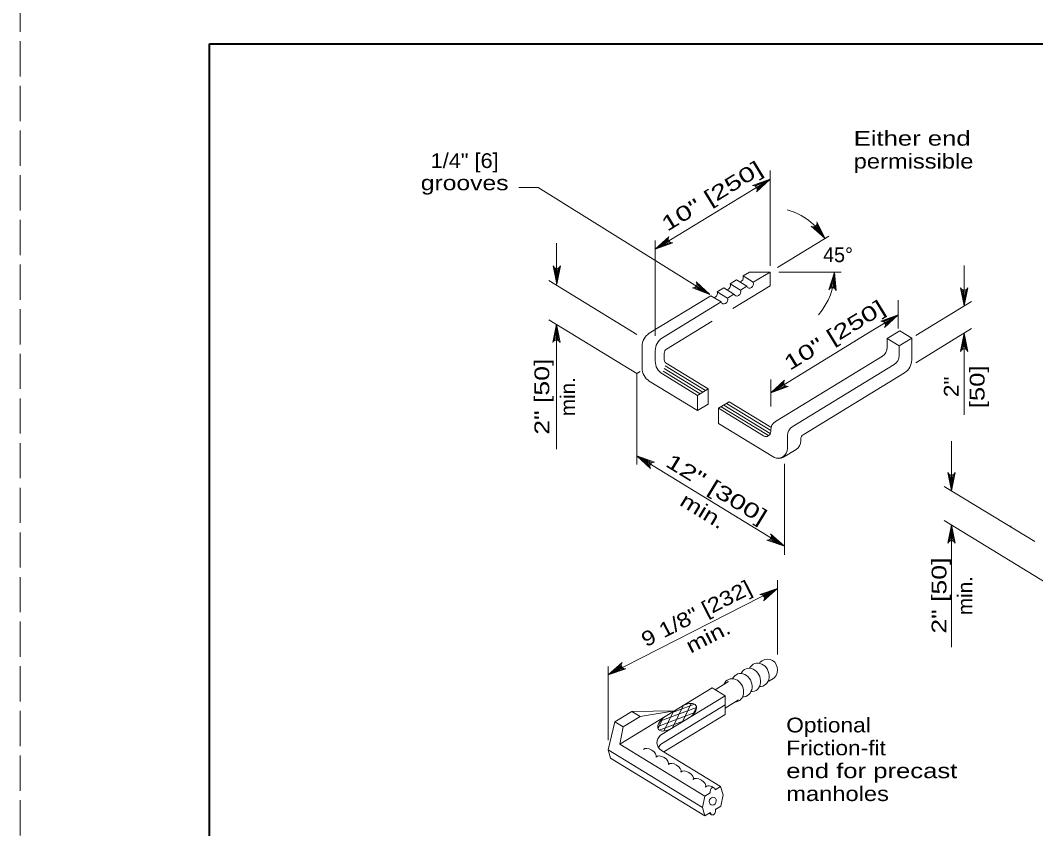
# Model space of a CAD drawing. Extents: x 1083.1 to 1117.1, y 697.4 to 741.4.
# Drawn here: x 1083.13 to 1093.86, y 710.56 to 719.1 of the extents above; entities that cross this region are included whole.
import ezdxf
from ezdxf.enums import TextEntityAlignment as Align

# ---------------------------------------------------------------- set-up
doc = ezdxf.new("R2010")
doc.units = 0
doc.header["$LTSCALE"] = 0.062
doc.linetypes.add('LONG_DASHED', pattern=[7.5, 6, -1.5])
doc.layers.add('1', color=7, linetype='Continuous', lineweight=13)

msp = doc.modelspace()

# ---------------------------------------------------------------- linework, layer by layer
at = {"layer": '1', "lineweight": 25}
msp.add_line((1085.12642, 718.85408), (1116.62642, 718.85408), dxfattribs=at)
at = {"layer": '1'}
for p, q in [((1091.05508, 716.509), (1091.05508, 717.51783)), ((1089.8405, 716.68325), (1091.05508, 717.42558)), ((1090.89017, 717.35567), (1091.05508, 717.42558)), ((1090.90183, 717.3495), (1091.05508, 717.42558)), ((1090.91275, 717.33775), (1091.05508, 717.42558)), ((1090.91767, 717.32633), (1091.05508, 717.42558)), ((1090.919, 717.31292), (1091.05508, 717.42558)), ((1091.53583, 716.92942), (1091.63758, 716.79667)), ((1091.54642, 716.94142), (1091.63758, 716.79667)), ((1091.55133, 716.95367), (1091.63758, 716.79667)), ((1091.13442, 716.49142), (1091.67692, 716.82292)), ((1091.51167, 716.92067), (1091.63758, 716.79667)), ((1091.52492, 716.92333), (1091.63758, 716.79667)), ((1088.79483, 716.3145), (1088.79483, 716.74958)), ((1089.9775, 716.79483), (1089.8405, 716.68325)), ((1089.97867, 716.78142), (1089.8405, 716.68325)), ((1089.8405, 715.76658), (1089.8405, 716.77542)), ((1089.98358, 716.76992), (1089.8405, 716.68325)), ((1089.99433, 716.75808), (1089.8405, 716.68325)), ((1090.006, 716.75183), (1089.8405, 716.68325)), ((1093.108, 716.51342), (1093.108, 716.084)), ((1088.77458, 716.4895), (1088.79908, 716.3145)), ((1088.78675, 716.48358), (1088.79908, 716.3145)), ((1088.82617, 716.49158), (1088.79908, 716.3145)), ((1088.81483, 716.48483), (1088.79908, 716.3145)), ((1088.79908, 716.48175), (1088.79908, 716.3145)), ((1090.76908, 716.401), (1090.83725, 716.44267)), ((1090.87783, 716.3345), (1090.76908, 716.401)), ((1090.83725, 716.44267), (1091.05508, 716.44267)), ((1090.87783, 716.3345), (1091.05508, 716.44283)), ((1091.05508, 716.29775), (1091.05508, 716.44267)), ((1091.14675, 716.44283), (1091.80542, 716.44283)), ((1091.68933, 716.27008), (1091.73658, 716.44283)), ((1091.70133, 716.2755), (1091.73658, 716.44283)), ((1091.71733, 716.27675), (1091.73658, 716.44283)), ((1091.72942, 716.2735), (1091.73658, 716.44283)), ((1091.74075, 716.26617), (1091.73658, 716.44283)), ((1089.646, 715.78317), (1088.71617, 716.3515)), ((1090.27583, 716.29417), (1090.41817, 716.20633)), ((1090.2815, 716.30917), (1090.41817, 716.20633)), ((1090.28175, 716.32233), (1090.41817, 716.20633)), ((1090.63267, 716.31758), (1090.70083, 716.35933)), ((1090.74142, 716.25117), (1090.63267, 716.31758)), ((1090.66283, 716.058), (1091.05508, 716.29775)), ((1090.80958, 716.29283), (1090.70083, 716.35933)), ((1090.74142, 716.25117), (1090.80958, 716.29283)), ((1089.77725, 715.79475), (1090.428, 716.19258)), ((1090.25642, 716.27742), (1090.41817, 716.20633)), ((1090.26783, 716.28458), (1090.41817, 716.20633)), ((1090.53683, 716.12608), (1090.428, 716.19258)), ((1090.49625, 716.23425), (1090.56442, 716.27592)), ((1090.605, 716.16775), (1090.49625, 716.23425)), ((1090.67325, 716.2095), (1090.56442, 716.27592)), ((1090.605, 716.16775), (1090.67325, 716.2095)), ((1093.0835, 716.259), (1093.108, 716.084)), ((1093.09558, 716.25308), (1093.108, 716.084)), ((1093.135, 716.26108), (1093.108, 716.084)), ((1093.12367, 716.25442), (1093.108, 716.084)), ((1093.108, 716.25133), (1093.108, 716.084)), ((1089.91567, 715.74642), (1090.53683, 716.12608)), ((1092.41025, 715.84475), (1092.41025, 716.1435)), ((1092.5955, 715.77075), (1093.18667, 716.13208)), ((1092.24533, 715.92117), (1092.41025, 715.99092)), ((1092.25692, 715.915), (1092.41025, 715.99092)), ((1092.26783, 715.90325), (1092.41025, 715.99092)), ((1092.27275, 715.89175), (1092.41025, 715.99092)), ((1092.27408, 715.87833), (1092.41025, 715.99092)), ((1089.646, 715.37), (1088.71617, 715.93833)), ((1088.76783, 715.71325), (1088.79483, 715.89025)), ((1088.77917, 715.71992), (1088.79483, 715.89025)), ((1088.79483, 715.723), (1088.79483, 715.89025)), ((1088.80725, 715.72117), (1088.79483, 715.89025)), ((1088.81933, 715.71525), (1088.79483, 715.89025)), ((1088.79483, 714.56808), (1088.79483, 715.89025)), ((1089.96058, 715.62875), (1090.444, 715.92425)), ((1092.29283, 715.73975), (1092.42708, 715.82183)), ((1092.55308, 715.74483), (1092.42708, 715.82183)), ((1092.5955, 715.48325), (1093.18667, 715.84458)), ((1093.08092, 715.61942), (1093.108, 715.7965)), ((1093.09225, 715.62617), (1093.108, 715.7965)), ((1093.108, 715.62925), (1093.108, 715.7965)), ((1093.12033, 715.62742), (1093.108, 715.7965)), ((1093.13242, 715.6215), (1093.108, 715.7965)), ((1093.108, 715.7965), (1093.108, 714.933)), ((1089.70208, 715.42708), (1089.70208, 715.65692)), ((1092.41875, 715.66283), (1092.29283, 715.73975)), ((1092.29283, 715.6465), (1092.29283, 715.73975)), ((1092.41875, 715.66283), (1092.55308, 715.74483)), ((1092.41875, 715.55858), (1092.41875, 715.66283)), ((1092.55308, 715.51542), (1092.55308, 715.74483)), ((1089.8405, 715.50292), (1089.8405, 715.60858)), ((1089.93558, 715.51533), (1089.93558, 715.58317)), ((1091.11158, 714.86325), (1092.24275, 715.55467)), ((1090.37142, 715.19008), (1089.9455, 715.45042)), ((1090.39967, 715.20733), (1089.9555, 715.47883)), ((1091.28925, 714.80692), (1092.36867, 715.46667)), ((1089.646, 715.37), (1089.68242, 715.39225)), ((1089.646, 715.37), (1089.646, 714.40642)), ((1090.28675, 715.13833), (1089.91567, 715.36508)), ((1090.315, 715.15558), (1089.92558, 715.3935)), ((1090.34317, 715.17283), (1089.93558, 715.422)), ((1091.40467, 714.72158), (1092.47792, 715.37758)), ((1090.28675, 714.97833), (1089.77683, 715.29)), ((1091.0615, 715.02033), (1091.0615, 715.30717)), ((1091.19875, 715.27775), (1091.0615, 715.16642)), ((1091.19992, 715.26425), (1091.0615, 715.16642)), ((1091.20475, 715.25275), (1091.0615, 715.16642)), ((1091.2155, 715.24092), (1091.0615, 715.16642)), ((1091.22708, 715.23467), (1091.0615, 715.16642)), ((1090.28675, 715.13833), (1090.39967, 715.20733)), ((1090.28675, 714.97833), (1090.28675, 715.13833)), ((1090.39967, 715.04733), (1090.39967, 715.20733)), ((1090.28675, 714.97833), (1090.39967, 715.04733)), ((1090.50992, 715.00192), (1090.62275, 715.07092)), ((1090.98633, 714.71067), (1090.50992, 715.00192)), ((1090.50992, 714.84192), (1090.50992, 715.00192)), ((1091.0395, 714.71267), (1090.53808, 715.01917)), ((1091.05758, 714.73617), (1090.56633, 715.03642)), ((1091.0615, 714.76825), (1090.59458, 715.05367)), ((1091.0615, 714.80275), (1090.62275, 715.07092)), ((1091.09558, 714.48392), (1090.50992, 714.84192)), ((1091.0615, 714.75658), (1091.0615, 714.77133)), ((1091.23917, 714.57992), (1091.23917, 714.715)), ((1091.37958, 714.6575), (1091.37958, 714.67567)), ((1092.97308, 714.1285), (1092.97308, 714.65542)), ((1089.78908, 714.412), (1089.646, 714.49867)), ((1089.78358, 714.397), (1089.646, 714.49867)), ((1089.78342, 714.38383), (1089.646, 714.49867)), ((1089.797, 714.42167), (1089.646, 714.49867)), ((1089.80833, 714.429), (1089.646, 714.49867)), ((1089.646, 714.49867), (1091.20825, 713.54367)), ((1091.19583, 714.48392), (1091.3295, 714.56567)), ((1091.20825, 714.41508), (1091.20825, 713.4515)), ((1092.94867, 714.30342), (1092.97308, 714.1285)), ((1092.96075, 714.2975), (1092.97308, 714.1285)), ((1093.00017, 714.3055), (1092.97308, 714.1285)), ((1092.98883, 714.29883), (1092.97308, 714.1285)), ((1092.97308, 714.29575), (1092.97308, 714.1285)), ((1093.855, 713.59333), (1092.89442, 714.17617)), ((1095.45392, 712.25225), (1092.89442, 713.81675)), ((1092.94867, 713.59367), (1092.97308, 713.76867)), ((1092.96075, 713.59958), (1092.97308, 713.76867)), ((1092.97308, 713.60142), (1092.97308, 713.76867)), ((1092.98883, 713.59825), (1092.97308, 713.76867)), ((1093.00017, 713.59158), (1092.97308, 713.76867)), ((1092.97308, 712.47642), (1092.97308, 713.76867)), ((1093.60242, 713.75908), (1093.60242, 713.74617)), ((1091.04442, 713.61), (1091.20825, 713.54367)), ((1091.05558, 713.6175), (1091.20825, 713.54367)), ((1091.06333, 713.62733), (1091.20825, 713.54367)), ((1091.06842, 713.65567), (1091.20825, 713.54367)), ((1091.06858, 713.6425), (1091.20825, 713.54367)), ((1091.135, 713.18517), (1091.135, 712.4)), ((1089.3425, 712.18342), (1091.135, 713.09683)), ((1090.96817, 713.03175), (1091.135, 713.09683)), ((1090.97958, 713.02533), (1091.135, 713.09683)), ((1090.99017, 713.01325), (1091.135, 713.09683)), ((1090.99475, 713.00167), (1091.135, 713.09683)), ((1090.99567, 712.98817), (1091.135, 713.09683)), ((1090.94192, 712.313), (1090.973, 712.332)), ((1089.48183, 712.29208), (1089.3425, 712.18342)), ((1089.48275, 712.27867), (1089.3425, 712.18342)), ((1089.3425, 711.49467), (1089.3425, 712.27167)), ((1089.48742, 712.267), (1089.3425, 712.18342)), ((1089.49792, 712.255), (1089.3425, 712.18342)), ((1089.50942, 712.2485), (1089.3425, 712.18342)), ((1090.473, 712.02642), (1090.614, 712.11258)), ((1091.04342, 712.11567), (1091.08475, 712.141)), ((1089.46767, 711.44975), (1090.442, 712.04533)), ((1090.579, 711.96158), (1090.442, 712.04533)), ((1089.89792, 711.54525), (1090.579, 711.96158)), ((1090.579, 711.76525), (1090.579, 711.96158)), ((1090.579, 711.83183), (1090.72008, 711.91808)), ((1089.41383, 711.68617), (1089.59375, 711.79608)), ((1089.59375, 711.79608), (1090.0435, 711.8025)), ((1090.0435, 711.8025), (1089.67975, 711.74358)), ((1089.86675, 711.63883), (1090.25883, 711.78583)), ((1089.89075, 711.69242), (1090.27792, 711.8375)), ((1089.90667, 711.45475), (1090.579, 711.86575)), ((1089.93292, 711.58975), (1090.02917, 711.793)), ((1090.01158, 711.78225), (1090.2565, 711.87408)), ((1090.02317, 711.62192), (1090.13425, 711.85658)), ((1090.1285, 711.68617), (1090.22108, 711.88175)), ((1090.23942, 711.762), (1090.27767, 711.84283)), ((1089.41383, 711.68617), (1089.3425, 711.39033)), ((1089.49983, 711.63358), (1089.41383, 711.68617)), ((1089.87017, 711.61558), (1089.92208, 711.72517)), ((1089.88275, 711.60033), (1090.15492, 711.70233)), ((1089.93008, 711.36858), (1090.579, 711.76525)), ((1089.46767, 711.44975), (1089.49983, 711.63358)), ((1090.33992, 710.78075), (1089.3425, 711.39033)), ((1089.3425, 711.39033), (1089.369, 711.30217)), ((1090.36542, 710.901), (1089.46767, 711.44975)), ((1090.53058, 711.00158), (1089.906, 711.38333)), ((1090.36642, 710.69258), (1089.369, 711.30217)), ((1090.36567, 710.90083), (1090.42142, 710.93483)), ((1090.47483, 710.9675), (1090.53058, 711.00158)), ((1090.36542, 710.901), (1090.33992, 710.78075)), ((1090.33992, 710.78075), (1090.36642, 710.69258)), ((1090.36642, 710.69258), (1090.42325, 710.72733)), ((1090.437, 710.70433), (1090.41133, 710.72008)), ((1090.47667, 710.76), (1090.53358, 710.79475))]:
    msp.add_line(p, q, dxfattribs=at)
at = {"layer": '1', "linetype": 'LONG_DASHED'}
msp.add_lwpolyline([(1083.12642, 697.35408), (1117.12642, 697.35408), (1117.12642, 719.35408), (1083.12642, 719.35408)], close=True, dxfattribs=at)
at = {"layer": '1', "lineweight": 25}
msp.add_lwpolyline([(1116.62642, 697.85408), (1085.12642, 697.85408), (1085.12642, 718.85408)], dxfattribs=at)
at = {"layer": '1', "lineweight": 40}
msp.add_lwpolyline([(1085.12642, 718.85408), (1116.62642, 718.85408), (1116.62642, 697.85408), (1085.12642, 697.85408)], close=True, dxfattribs=at)
at = {"layer": '1'}
for points in [[(1090.87025, 717.357), (1091.05508, 717.42558), (1090.91092, 717.29117)], [(1090.41817, 716.20633), (1088.60167, 717.33642), (1088.39783, 717.33642)], [(1091.55067, 716.97358), (1091.63758, 716.79667), (1091.48933, 716.92658)], [(1090.02583, 716.75033), (1089.8405, 716.68325), (1089.98575, 716.8165)], [(1088.83775, 716.50783), (1088.79908, 716.3145), (1088.76042, 716.50783)], [(1091.67592, 716.25533), (1091.73658, 716.44283), (1091.75267, 716.24642)], [(1090.274, 716.34075), (1090.41817, 716.20633), (1090.23342, 716.275)], [(1093.14667, 716.27733), (1093.108, 716.084), (1093.06933, 716.27733)], [(1091.0615, 715.16642), (1092.07833, 715.788), (1092.41025, 715.99092)], [(1092.22542, 715.92258), (1092.41025, 715.99092), (1092.26592, 715.85667)], [(1088.75617, 715.697), (1088.79483, 715.89025), (1088.8335, 715.697)], [(1093.06933, 715.60325), (1093.108, 715.7965), (1093.14667, 715.60325)], [(1091.247, 715.23308), (1091.0615, 715.16642), (1091.20708, 715.29933)], [(1089.79133, 714.3655), (1089.646, 714.49867), (1089.83133, 714.43167)], [(1093.01175, 714.32175), (1092.97308, 714.1285), (1092.9345, 714.32175)], [(1093.01175, 713.57533), (1092.97308, 713.76867), (1092.9345, 713.57533)], [(1091.06017, 713.67383), (1091.20825, 713.54367), (1091.0215, 713.60683)], [(1090.94825, 713.03367), (1091.135, 713.09683), (1090.98692, 712.96675)], [(1089.52925, 712.24658), (1089.3425, 712.18342), (1089.49058, 712.3135)], [(1089.49983, 711.63358), (1089.67975, 711.74358), (1089.59375, 711.79608)], [(1090.53058, 711.00158), (1090.55817, 710.91417), (1090.53358, 710.79475)]]:
    msp.add_lwpolyline(points, dxfattribs=at)
for centre, radius, start, end in [((1090.87731, 717.31587), 0.04172, 323.77224, 99.59836), ((1091.05505, 716.44286), 0.68155, 31.27446, 74.61214), ((1091.51044, 716.96244), 0.04172, 239.55992, 15.38605), ((1090.01915, 716.79155), 0.04172, 143.31059, 279.13672), ((1088.79905, 716.52342), 0.04172, 202.08782, 337.91395), ((1091.05505, 716.44286), 0.68155, 318.5438, 0), ((1090.24041, 716.31604), 0.04172, 260.393, 36.21913), ((1091.71254, 716.23535), 0.04172, 15.45965, 151.28578), ((1093.10793, 716.29294), 0.04172, 202.08782, 337.91395), ((1092.23237, 715.88141), 0.04172, 323.68447, 99.5106), ((1088.79491, 715.68136), 0.04172, 22.08782, 157.91395), ((1093.10801, 715.58761), 0.04172, 22.08782, 157.91395), ((1091.24039, 715.27428), 0.04172, 143.15536, 278.98149), ((1089.82472, 714.39051), 0.04172, 80.90657, 216.7327), ((1092.97308, 714.33736), 0.04172, 202.08782, 337.91395), ((1091.02729, 713.64812), 0.04172, 262.08782, 37.91395), ((1092.97308, 713.55974), 0.04172, 22.08605, 157.91218), ((1090.95412, 712.99239), 0.04172, 322.08782, 97.91395), ((1089.52343, 712.2879), 0.04172, 142.08782, 277.91395)]:
    msp.add_arc(centre, radius, start, end, dxfattribs=at)
for centre, major_axis, ratio, start_param, end_param in [((1090.7349, 716.38035), (-0.01622, -0.0397), 0.836208, 0.44657163, 2.41466889), ((1090.59848, 716.29697), (-0.01622, -0.0397), 0.836208, 0.44657163, 2.41466889), ((1090.84365, 716.31388), (-0.01622, -0.0397), 0.836208, 5.56708016, 8.69785148), ((1090.46207, 716.21359), (-0.01622, -0.0397), 0.836208, 0.44657163, 2.41466889), ((1090.70723, 716.2305), (-0.01622, -0.0397), 0.836208, 5.56708016, 8.69785148), ((1090.57082, 716.14712), (-0.01622, -0.0397), 0.836208, 5.56708016, 8.69785148), ((1089.85241, 715.65695), (0, 0.15913), 0.944544, 0.52359902, 1.57078915), ((1089.99083, 715.60861), (0, 0.15913), 0.944544, 0.52359916, 1.5707956), ((1092.19263, 715.6465), (0, -0.10608), 0.944544, 0.52359882, 1.57078455), ((1089.98566, 715.5828), (0, 0.05304), 0.944544, 0.51976807, 1.57561111), ((1092.31857, 715.55856), (0, -0.10608), 0.944544, 0.52359892, 1.57079865), ((1089.85241, 715.42757), (0, 0.15913), 0.944544, 1.56615671, 2.62169853), ((1089.99083, 715.50292), (0, -0.15913), 0.944544, 4.71239368, 5.75959201), ((1089.97535, 715.51531), (0, 0.04213), 0.944544, 1.5707669, 2.61799669), ((1092.40275, 715.51543), (0, -0.15913), 0.944544, 0.52359848, 1.57078968), ((1091.16167, 714.77134), (0, 0.10608), 0.944544, 0.52359853, 1.57080088), ((1091.33934, 714.71502), (0, -0.10608), 0.944544, 3.66519157, 4.71239102), ((1091.01137, 714.75662), (0, -0.05304), 0.944544, 5.7595893, 7.85398202), ((1091.42972, 714.67568), (0, 0.05304), 0.944544, 0.52359848, 1.57079492), ((1091.13894, 714.57994), (0, 0.10608), 0.944544, 2.61799625, 4.71239111), ((1091.27942, 714.6575), (0, 0.10608), 0.944544, 3.66519376, 4.71241695), ((1091.14573, 714.57578), (0, -0.10608), 0.944544, 5.75958789, 6.80678573), ((1091.14573, 714.57578), (0, -0.10608), 0.944544, 5.75958847, 6.80678646), ((1090.9351, 712.18396), (0.04509, -0.11803), 0.84831, 5.92777232, 10.09288316), ((1091.02889, 712.23652), (0, 0.11235), 0.944544, 3.63436833, 6.8376226), ((1090.75511, 712.07395), (0.04509, -0.11803), 0.84831, 5.92780713, 10.09285582), ((1090.8451, 712.12895), (0.04509, -0.11803), 0.84831, 5.92780713, 10.09285582), ((1090.66512, 712.01894), (0.04509, -0.11803), 0.84831, 6.01711466, 10.14097445), ((1090.15487, 711.78526), (-0.11672, -0.07513), 0.518617, 1.71301598, 4.57774803), ((1089.98958, 711.68584), (-0.11672, -0.07513), 0.518617, 4.8564823, 7.85408437), ((1089.99429, 711.46713), (0.13528, -0.00111), 0.819908, 2.37070385, 4.00778157), ((1090.00122, 711.37516), (0.13528, -0.00111), 0.819908, 2.35146964, 2.78176084), ((1089.78283, 711.35313), (-0.06542, 0.03968), 0.537699, 3.15958152, 6.25223664), ((1089.91371, 711.27401), (-0.06542, 0.03968), 0.537699, 3.15958152, 6.25223664), ((1090.0446, 711.1949), (-0.06542, 0.03968), 0.537699, 3.15958152, 6.25223664), ((1090.17548, 711.11578), (-0.06542, 0.03968), 0.537699, 3.15958152, 6.25223664), ((1090.30637, 711.03667), (-0.06542, 0.03968), 0.537699, 3.15958152, 6.25223664), ((1090.43694, 710.95698), (-0.06542, 0.03968), 0.537699, 4.61023244, 6.25495553), ((1090.44812, 710.9512), (-0.00616, -0.04177), 0.647013, 2.06564711, 5.20714963), ((1090.44999, 710.74366), (-0.00616, -0.04177), 0.647013, 5.20714963, 8.34874229), ((1090.44999, 710.74366), (-0.00616, -0.04177), 0.647013, 2.06556721, 2.18205703)]:
    msp.add_ellipse(centre, major_axis=major_axis, ratio=ratio, start_param=start_param, end_param=end_param, dxfattribs=at)
msp.add_ellipse((1090.44906, 710.84743), major_axis=(-0.01622, -0.0397), ratio=0.836208, dxfattribs=at)

# ---------------------------------------------------------------- texts
for s, width, p in [('Either end', 1.3, (1091.93908, 717.77858)), ('permissible', 1.2, (1091.93908, 717.53667)), ('Optional', 1.15, (1091.22608, 711.57525)), ('Friction-fit', 1.15, (1091.22608, 711.33333)), ('end for precast', 1.3, (1091.22608, 711.09142)), ('manholes', 1.2, (1091.22608, 710.8495))]:
    msp.add_text(s, height=0.156, dxfattribs=dict(at, width=width)).set_placement(p)
for s, width, p in [('1/4" [6]', 1.1, (1087.82529, 717.54233)), ('grooves', 1.25, (1087.82529, 717.30767))]:
    msp.add_text(s, height=0.156, dxfattribs=dict(at, width=width)).set_placement(p, align=Align.CENTER)
for s, rotation, width, p in [('10" [250]', 31.435, 1.45, (1090.47915, 717.17937)), ('10" [250]', 31.435, 1.45, (1091.77474, 715.70937)), ('2" [50]', 90, 1.35, (1088.71958, 715.12487)), ('[50]', 90, 1.3, (1093.323, 715.22896)), ('2"', 90, 1.15, (1093.049, 715.22896)), ('min.', 90, 1.05, (1088.99358, 715.12483)), ('12" [300]', 328.565, 1.45, (1090.44861, 714.08438)), ('min.', 328.565, 1.3, (1090.30565, 713.85056)), ('2" [50]', 90, 1.35, (1092.91967, 713.02171)), ('9 1/8" [232]', 27.003, 1.2, (1090.3105, 712.76303)), ('min.', 90, 1.05, (1093.19367, 713.02167)), ('min.', 27.003, 1.25, (1090.43488, 712.51897))]:
    msp.add_text(s, height=0.156, rotation=rotation, dxfattribs=dict(at, width=width)).set_placement(p, align=Align.CENTER)
msp.add_text('45°', height=0.156, dxfattribs=at).set_placement((1091.61533, 716.54717))

doc.saveas('drawing.dxf')
